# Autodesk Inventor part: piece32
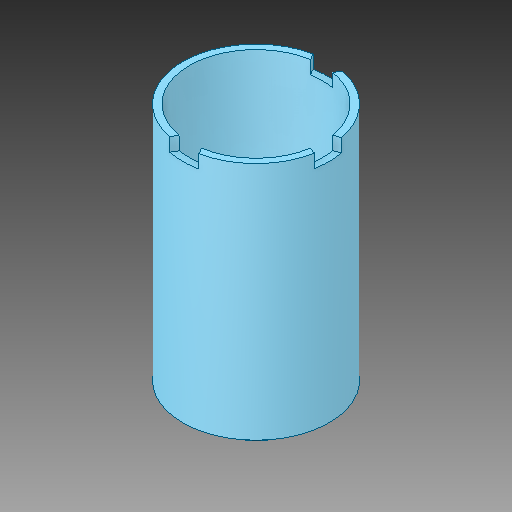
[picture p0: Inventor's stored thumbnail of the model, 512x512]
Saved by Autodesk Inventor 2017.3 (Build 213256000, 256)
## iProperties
Created: 2002-06
Part Number: piece32
Material: Générique
Document SubType Name: Modeling
Designer: ficho
Density: 1 g/cm^3
Appearance: Par défaut
Author: ficho
Sending System: SolidWorks 2009
Last Author: christophe
Last Saved: 2011-02-10
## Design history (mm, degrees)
feature "Répétition circulaire1"
node "Solide1"
